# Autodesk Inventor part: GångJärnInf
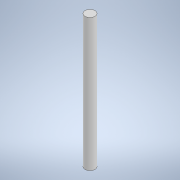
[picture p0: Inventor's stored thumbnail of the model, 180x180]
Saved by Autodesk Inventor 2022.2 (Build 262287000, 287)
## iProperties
Created: 2022-03
Part Number: GångJärnInf
Material: Generic
Document SubType Name: Modeling
Designer: cl
Density: 1 g/cm^3
Appearance: Default
Author: cl
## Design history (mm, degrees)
sketch "Sketch1"
  geometry: C1 r 3.75 at (0, 0); 1 further point
  constraints: 1 centre point, 1 coincident
  dimensions: "d0" = 7.5 diameter of C1
extrude "Extrusion1" new body sketch "Sketch1" distance "d1" = 100; taper "d2" = 0 deg
body "Solid1"
